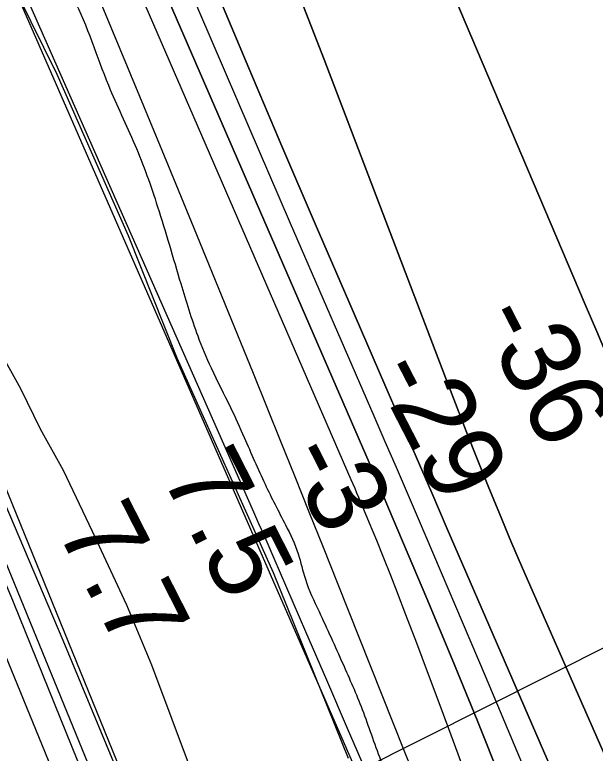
# Model space of a CAD drawing. Extents: x 3684037 to 3722149, y 433263 to 459021.
# Drawn here: x 3708229 to 3708721, y 440941 to 441568 of the extents above; entities that cross this region are included whole.
import ezdxf

# ---------------------------------------------------------------- set-up
doc = ezdxf.new("R2010")
doc.units = 0
for name, color, linetype in [('V-FLOD-BASE', 7, 'Continuous'), ('V-LEVE-TOET', 7, 'Continuous'), ('V-RIVR-EDGE', 7, 'Continuous'), ('V-RIVR-RANG', 7, 'Continuous'), ('V-RRAP-FSHR', 7, 'Continuous'), ('V-SITE-VEGE', 7, 'Continuous'), ('V-SURV-LINE', 7, 'Continuous'), ('V-TOPO-DPTH', 7, 'Continuous'), ('V-TOPO-MINR', 7, 'Continuous'), ('V-TOPO-WATR', 7, 'Continuous'), ('V-UTIL-IDEN', 7, 'Continuous')]:
    doc.layers.add(name, color=color, linetype=linetype)

msp = doc.modelspace()

# ---------------------------------------------------------------- linework, layer by layer
at = {"layer": 'V-FLOD-BASE'}
msp.add_lwpolyline([(3708655.953, 440022.846), (3708571.096, 440224.43700000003), (3708471.115, 440472.954), (3708336.848, 440799.67100000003), (3708227.5670000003, 441069.62), (3708110.161, 441351.732), (3708024.131, 441566.072), (3707971.184, 441738.141), (3707949.653, 441811.721)], dxfattribs=at)
at = {"layer": 'V-LEVE-TOET'}
msp.add_lwpolyline([(3708329.4450000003, 440893.404), (3708269.701, 441036.97500000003), (3708174.0530000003, 441261.768), (3708096.1550000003, 441453.563), (3708080.201, 441490.052), (3708065.4560000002, 441529.456), (3708040.023, 441605.28500000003), (3707987.7630000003, 441786.817), (3707911.21, 442041.826), (3707839.258, 442289.753)], dxfattribs=at)
at = {"layer": 'V-RIVR-EDGE'}
msp.add_spline([(3705459.2609885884, 448025.4338505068), (3705478.181262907, 447991.0156329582), (3705490.6466582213, 447962.67892349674), (3705497.886274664, 447946.89059973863), (3705515.196078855, 447915.30695303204), (3705550.2240541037, 447853.7561290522), (3705577.199678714, 447806.37815928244), (3705592.0892782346, 447777.22671585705), (3705613.0133912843, 447735.5248869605), (3705627.0852571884, 447702.7361373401), (3705648.4127376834, 447660.6289412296), (3705670.9403216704, 447613.2619701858), (3705688.6394949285, 447575.6118136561), (3705703.1157281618, 447542.82206415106), (3705728.0505183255, 447487.76611454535), (3705750.155737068, 447433.12153145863), (3705764.2256032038, 447399.5240471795), (3705787.557922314, 447350.5376070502), (3705800.426685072, 447321.79553037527), (3705823.7710027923, 447277.66149819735), (3705853.129836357, 447212.8897339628), (3705867.200702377, 447179.69661701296), (3705884.5115064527, 447148.517337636), (3705906.216357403, 447095.49122375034), (3705936.00155575, 447039.61454087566), (3705952.47362864, 446996.3062413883), (3705954.4714680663, 446986.5964260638), (3705964.512659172, 446959.0744505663), (3705978.185157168, 446928.3085374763), (3706001.9328423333, 446883.76913808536), (3706017.2158104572, 446850.1686541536), (3706031.3046743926, 446824.25414913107), (3706060.2971362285, 446774.8493432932), (3706084.8695541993, 446736.77782140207), (3706095.754475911, 446723.40670266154), (3706096.150844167, 446720.17076414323), (3706091.2844378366, 446714.52162014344), (3706089.663968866, 446713.31251769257), (3706090.461704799, 446708.86247730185), (3706096.1148483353, 446705.61354028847), (3706102.9840935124, 446703.5747056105), (3706108.6282380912, 446696.68646263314), (3706116.2782211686, 446683.3233429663), (3706129.961717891, 446657.0054704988), (3706163.363224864, 446591.8193400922), (3706169.3887394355, 446575.6296486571), (3706187.0869128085, 446537.5751247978), (3706212.808440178, 446473.6210941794), (3706230.094247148, 446432.33263156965), (3706247.398052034, 446398.3227808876), (3706265.123222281, 446371.18617491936), (3706278.8077188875, 446345.27266978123), (3706293.681320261, 446309.65134908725), (3706314.591434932, 446262.28837758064), (3706333.5067098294, 446225.8483233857), (3706356.038293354, 446180.09882165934), (3706380.1853464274, 446133.5365857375), (3706396.283048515, 446102.36030601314), (3706412.7941168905, 446074.82233236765), (3706429.688555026, 446038.79164492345), (3706446.9753618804, 445997.9075496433), (3706455.379085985, 445962.3022270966), (3706478.2400455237, 445886.2241757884), (3706492.7132791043, 445852.221324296), (3706510.4004537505, 445809.7187598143), (3706528.098627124, 445771.6642359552), (3706558.2621958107, 445705.27300263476), (3706582.809616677, 445657.09229751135), (3706597.6902172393, 445624.3015481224), (3706628.25915314, 445558.3136822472), (3706659.6138263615, 445483.02336802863), (3706677.6863705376, 445432.8368244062), (3706696.968017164, 445381.0298118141), (3706750.0515385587, 445262.4181996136), (3706782.6343120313, 445193.1903956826), (3706806.7693664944, 445141.77575180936), (3706827.6774813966, 445093.60404564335), (3706850.971804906, 445029.251647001), (3706864.204939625, 444984.33387727), (3706871.8019288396, 444949.5392891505), (3706889.464106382, 444896.92754143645), (3706899.900665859, 444865.76526009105), (3706912.3530626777, 444832.1717753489), (3706928.848132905, 444798.1639244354), (3706942.5356291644, 444773.46352128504), (3706966.274315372, 444725.28481592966), (3706990.4233682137, 444679.53131466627), (3707016.9756276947, 444624.4713655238), (3707033.864066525, 444586.0144741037), (3707080.5137064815, 444481.9760839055), (3707095.3833083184, 444444.7372938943), (3707112.268747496, 444405.0673004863), (3707123.1276722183, 444381.1826311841), (3707171.385782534, 444273.5009354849), (3707203.15082239, 444200.6358253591), (3707218.0214241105, 444163.8014026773), (3707250.203829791, 444096.19206794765), (3707257.428447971, 444074.33823424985), (3707269.882844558, 444041.55348416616), (3707288.3577562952, 443990.55720600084), (3707304.028093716, 443950.0814775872), (3707342.974756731, 443837.9747386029), (3707365.860713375, 443772.0058705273), (3707378.693480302, 443728.70656999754), (3707379.8705864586, 443714.14634649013), (3707381.055691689, 443702.8210616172), (3707387.4745748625, 443682.1823296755), (3707398.330499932, 443657.0845583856), (3707418.0505099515, 443619.02503510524), (3707438.977622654, 443578.5363081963), (3707454.253591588, 443542.10525295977), (3707473.1368701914, 443492.7254442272), (3707483.176061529, 443464.3947340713), (3707531.0578012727, 443368.0363234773), (3707542.7274604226, 443344.9583890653), (3707550.7628130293, 443323.91129025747), (3707556.775329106, 443302.4648235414), (3707556.7633304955, 443297.61241559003), (3707558.764169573, 443289.1157022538), (3707568.429989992, 443273.3213791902), (3707583.724956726, 443244.5733032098), (3707593.778146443, 443221.9037356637), (3707598.205189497, 443213.40102302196), (3707609.506477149, 443204.8813123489), (3707611.9086839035, 443195.17049714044), (3707611.872688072, 443180.6132732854), (3707615.480997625, 443168.06888711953), (3707621.9068799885, 443150.26072648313), (3707634.3842739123, 443126.77642497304), (3707648.071770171, 443102.0760218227), (3707655.300387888, 443081.8396574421), (3707660.5361656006, 443073.3349450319), (3707674.23066105, 443051.46511318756), (3707678.635706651, 443034.0663193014), (3707682.6333852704, 443015.4554233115), (3707689.4656347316, 442998.4549974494), (3707701.917031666, 442964.4571453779), (3707713.9590618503, 442928.4384565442), (3707721.175680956, 442903.349684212), (3707726.3964604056, 442888.7794618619), (3707738.081117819, 442871.7670373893), (3707743.706264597, 442857.1958151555), (3707744.4850027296, 442845.0627955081), (3707747.2685794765, 442826.050531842), (3707753.7124597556, 442815.5209831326), (3707762.977912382, 442801.34512927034), (3707770.2135292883, 442783.9393361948), (3707772.585739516, 442762.0975011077), (3707776.166052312, 442738.23082972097), (3707779.760363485, 442720.02530094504), (3707786.591613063, 442702.6205077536), (3707805.499888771, 442663.34988225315), (3707822.7986942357, 442627.3181949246), (3707832.0301507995, 442599.39385186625), (3707839.2457700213, 442573.9007122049), (3707845.6846508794, 442561.3493268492), (3707852.5368980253, 442552.4362475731), (3707860.193880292, 442541.9036992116), (3707869.4663321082, 442530.55841665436), (3707886.3937664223, 442507.8718510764), (3707898.8601616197, 442479.9395089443), (3707916.135969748, 442434.60737304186), (3707928.5753680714, 442395.7571130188), (3707943.439970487, 442356.49648636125), (3707965.5811850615, 442316.40912712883), (3707989.726238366, 442269.0381565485), (3708009.8426166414, 442227.7426947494), (3708024.7172178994, 442192.5257413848), (3708061.3216672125, 442114.39185736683), (3708074.19742916, 442088.4803519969), (3708094.3098078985, 442045.5674208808), (3708116.024657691, 441996.5849802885), (3708126.0638490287, 441968.25427013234), (3708137.690513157, 441927.7885405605), (3708147.3253371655, 441899.4588302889), (3708157.761896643, 441868.2965489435), (3708179.0553810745, 441812.4408636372), (3708203.964174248, 441746.87136346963), (3708227.690861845, 441693.8402501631), (3708249.813078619, 441646.06991167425), (3708265.103045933, 441615.29999904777), (3708271.524928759, 441595.87436909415), (3708278.365177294, 441582.10888186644), (3708308.1063807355, 441508.4400365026), (3708330.6259656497, 441457.8381268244), (3708349.905612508, 441405.22237957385), (3708369.558630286, 441340.0702452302), (3708384.005866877, 441295.5538431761), (3708395.2611598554, 441268.4332353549), (3708411.757229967, 441234.82975177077), (3708423.4208898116, 441209.32561338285), (3708441.1150636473, 441169.65362020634), (3708458.4178686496, 441135.239402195), (3708469.274793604, 441110.54599823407), (3708475.28730968, 441089.09953151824), (3708486.945970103, 441061.5735564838), (3708507.055349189, 441017.44752338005), (3708523.5384208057, 440978.58726451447), (3708539.202758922, 440935.68533212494), (3708564.1435483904, 440883.0555864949), (3708587.089498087, 440841.3487581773), (3708595.1408488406, 440826.77153663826), (3708600.3546291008, 440809.3707429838), (3708606.7475152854, 440778.2184604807), (3708615.5866031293, 440755.14752525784), (3708636.8620896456, 440692.013228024), (3708652.91879648, 440644.25788779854), (3708673.412545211, 440592.04350822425), (3708688.685514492, 440554.3993509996), (3708705.9553233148, 440506.6410111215), (3708725.6613349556, 440462.92034523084), (3708743.353509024, 440422.43961739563), (3708759.4422121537, 440387.62403170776), (3708800.050339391, 440293.3054556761), (3708820.961453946, 440246.3468514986), (3708835.028320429, 440211.5362652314), (3708849.1041858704, 440180.3649849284), (3708876.059812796, 440124.89966857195), (3708892.157514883, 440093.72338884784), (3708912.2798924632, 440054.8541310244), (3708922.3300825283, 440030.97146149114), (3708931.9579073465, 439999.8111799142), (3708939.1845252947, 439978.7660808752), (3708948.0196136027, 439954.0776763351), (3708952.412660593, 439931.82647449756), (3708956.0019723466, 439911.59910907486), (3708960.015649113, 439899.45809035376), (3708969.6484733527, 439870.3196454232), (3708986.9362800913, 439829.8399174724), (3708999.3836774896, 439794.22459608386), (3709014.653647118, 439755.36733687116), (3709034.7480279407, 439705.1757938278), (3709046.79605743, 439671.58330896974), (3709063.280128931, 439633.1274174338), (3709075.7695214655, 439614.49552387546), (3709093.103322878, 439592.6166930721), (3709105.998082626, 439574.38816695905), (3709121.705415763, 439548.8740297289), (3709151.4686166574, 439484.1012656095), (3709171.5959936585, 439447.2538444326), (3709197.377514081, 439407.5618535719), (3709211.0500120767, 439376.7959404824), (3709222.3063049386, 439350.0796999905), (3709240.400846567, 439308.789237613), (3709252.8692415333, 439281.6656301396), (3709266.1473710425, 439254.94439022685), (3709270.9767816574, 439245.6319430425), (3709296.338936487, 439199.87544212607), (3709313.2213760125, 439158.99234673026), (3709331.3089184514, 439114.8713130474), (3709341.338110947, 439082.49692959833), (3709360.25438573, 439046.46124273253), (3709378.7622936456, 439008.80908643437), (3709407.717759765, 438944.44268941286), (3709416.407475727, 438923.6321006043)], degree=3, dxfattribs=at)
at = {"layer": 'V-RIVR-RANG'}
msp.add_line((3708319.1132000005, 440825.27049999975), (3708998.1321000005, 441166.64039999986), dxfattribs=at)
at = {"layer": 'V-RRAP-FSHR'}
for points in [[(3707275.154863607, 443771.4072567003), (3708786.0361450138, 440314.0350934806), (3709222.0934795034, 438921.3709975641)], [(3709200.4250000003, 438921.235), (3709188.2, 438975.89), (3709081.992, 439212.059), (3708987.099, 439411.844), (3708916.306, 439573.43200000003), (3708676.386, 440059.424), (3708454.74, 440592.12200000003), (3708052.683, 441579.782), (3707944.372, 441937.206), (3707632.811, 442977.512), (3707556.2430000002, 443134.009), (3707319.723, 443635.882)]]:
    msp.add_lwpolyline(points, dxfattribs=at)
at = {"layer": 'V-SITE-VEGE'}
for points in [[(3708269.934, 441181.261), (3708250.458, 441216.37), (3708233.971, 441250.735), (3708216.7430000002, 441281.363), (3708192.008, 441338.893), (3708174.759, 441385.219), (3708162.008, 441421.08400000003), (3708153.761, 441441.256), (3708141.0160000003, 441472.63800000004), (3708104.3000000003, 441548.84), (3708090.8000000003, 441586.197), (3708079.546, 441622.814), (3708069.031, 441661.672), (3708007.526, 441838.01300000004), (3707976.744, 441950.852), (3707954.046, 442061.657), (3707919.329, 442186.782)], [(3708008.644, 442157.204), (3708091.0640000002, 441994.341), (3708103.063, 441960.717), (3708127.827, 441879.268), (3708146.603, 441805.286), (3708169.113, 441733.55100000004), (3708199.856, 441653.605), (3708230.5840000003, 441586.365), (3708264.304, 441517.634), (3708325.015, 441380.912), (3708366.251, 441277.056), (3708447.946, 441094.759), (3708511.6720000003, 440937.11)], [(3708413.122, 440833.836), (3708344.883, 441016.147), (3708323.893, 441066.954), (3708294.664, 441129.71), (3708269.934, 441181.261)]]:
    msp.add_lwpolyline(points, dxfattribs=at)
at = {"layer": 'V-SURV-LINE'}
for points in [[(3708038.7450004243, 441548.75442255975), (3708670.0374785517, 440004.8612832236)], [(3708642.27273785, 439993.4982175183), (3708010.9802905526, 441537.39128145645)]]:
    msp.add_lwpolyline(points, dxfattribs=at)
at = {"layer": 'V-TOPO-DPTH'}
for points in [[(3707771.34, 442984.16000000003), (3708145.170398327, 442084.14554148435), (3708156.85360117, 442056.08693645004), (3708168.5694781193, 442028.0420147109), (3708180.3343662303, 442000.0176179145), (3708192.1319284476, 441972.006904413), (3708228.467923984, 441885.9454586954), (3708258.560119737, 441814.95798427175), (3708288.788486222, 441744.0287745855), (3708319.221108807, 441673.1869620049), (3708349.7899021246, 441602.40341416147), (3708523.7871581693, 441201.093698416), (3708529.3498738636, 441188.21904241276), (3708534.8907832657, 441175.33504113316), (3708540.398983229, 441162.4370219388), (3708545.8853769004, 441149.5296574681), (3708578.464186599, 441072.6133977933), (3708599.970032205, 441021.1383346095), (3708621.13782245, 440969.52655543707), (3708641.7985296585, 440917.70970228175)], [(3708641.7985296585, 440917.70970228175), (3708621.13782245, 440969.52655543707), (3708599.970032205, 441021.1383346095), (3708578.464186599, 441072.6133977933), (3708545.8853769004, 441149.5296574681), (3708540.398983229, 441162.4370219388), (3708534.8907832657, 441175.33504113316), (3708529.3498738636, 441188.21904241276), (3708523.7871581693, 441201.093698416), (3708349.7899021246, 441602.40341416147), (3708319.221108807, 441673.1869620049), (3708288.788486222, 441744.0287745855), (3708258.560119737, 441814.95798427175), (3708228.467923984, 441885.9454586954), (3708192.1319284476, 441972.006904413), (3708180.3343662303, 442000.0176179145), (3708168.5694781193, 442028.0420147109), (3708156.85360117, 442056.08693645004), (3708145.170398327, 442084.14554148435), (3707771.34, 442984.16000000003)], [(3708709.870800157, 440868.57363529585), (3708595.781401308, 441131.8114475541), (3708582.5323741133, 441162.37974210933), (3708569.2828071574, 441192.94780270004), (3708556.032430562, 441223.5155123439), (3708542.7815142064, 441254.0829880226), (3708512.159733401, 441324.71935358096), (3708483.7195669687, 441390.6568542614), (3708455.4421222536, 441456.6637096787), (3708427.4087601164, 441522.7745972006), (3708399.5381196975, 441588.954839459), (3708215.8067283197, 442027.4975893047), (3708212.4666078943, 442035.48625685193), (3708209.1342115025, 442043.4781385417), (3708205.8134011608, 442051.474841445), (3708202.5003148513, 442059.47475849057), (3708154.4324801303, 442175.77970447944)], [(3708154.4324801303, 442175.77970447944), (3708202.5003148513, 442059.47475849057), (3708205.8134011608, 442051.474841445), (3708209.1342115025, 442043.4781385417), (3708212.4666078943, 442035.48625685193), (3708215.8067283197, 442027.4975893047), (3708399.5381196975, 441588.954839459), (3708427.4087601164, 441522.7745972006), (3708455.4421222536, 441456.6637096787), (3708483.7195669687, 441390.6568542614), (3708512.159733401, 441324.71935358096), (3708542.7815142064, 441254.0829880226), (3708556.032430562, 441223.5155123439), (3708569.2828071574, 441192.94780270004), (3708582.5323741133, 441162.37974210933), (3708595.781401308, 441131.8114475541), (3708709.870800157, 440868.57363529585)], [(3708068.57925163, 442138.1876600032), (3708086.3673393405, 442095.5563353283), (3708087.5154071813, 442092.804368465), (3708104.7195587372, 442051.5449005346), (3708121.9140457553, 442010.28140738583), (3708139.0940359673, 441969.01187641), (3708156.264361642, 441927.7383202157), (3708334.5443219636, 441498.98151528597), (3708358.826440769, 441440.3446441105), (3708382.995240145, 441381.6612939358), (3708406.9940603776, 441322.9082252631), (3708430.8795611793, 441264.10867759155), (3708454.2502159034, 441206.3368630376), (3708466.335495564, 441176.37638161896), (3708478.380905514, 441146.39992554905), (3708490.3665108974, 441116.39950750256), (3708502.3122465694, 441086.38311480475), (3708558.7794256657, 440944.08357560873), (3708599.490422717, 440843.14048317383)], [(3709009.52, 440303.11), (3708669.687304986, 441075.3251492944), (3708659.658509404, 441098.39599814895), (3708649.769239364, 441121.5257582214), (3708640.08925764, 441144.74388512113), (3708630.5488014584, 441168.020923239), (3708621.182264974, 441191.36938258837), (3708611.9080620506, 441214.7541449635), (3708602.772359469, 441238.19336187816), (3708593.7289904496, 441261.66888181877), (3708491.1548153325, 441530.3054668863), (3708456.1600394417, 441620.4667499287), (3708420.5087869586, 441710.3635082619), (3708383.872819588, 441799.8634795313), (3708346.5803756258, 441889.0989260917), (3708290.1373106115, 442022.10221289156), (3708280.546887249, 442044.62597398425), (3708270.920441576, 442067.13427770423), (3708261.2399624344, 442089.61939536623), (3708251.523460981, 442112.08905565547)], [(3708251.523460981, 442112.08905565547), (3708261.2399624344, 442089.61939536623), (3708270.920441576, 442067.13427770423), (3708280.546887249, 442044.62597398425), (3708290.1373106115, 442022.10221289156), (3708346.5803756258, 441889.0989260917), (3708383.872819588, 441799.8634795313), (3708420.5087869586, 441710.3635082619), (3708456.1600394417, 441620.4667499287), (3708491.1548153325, 441530.3054668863), (3708593.7289904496, 441261.66888181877), (3708602.772359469, 441238.19336187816), (3708611.9080620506, 441214.7541449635), (3708621.182264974, 441191.36938258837), (3708630.5488014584, 441168.020923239), (3708640.08925764, 441144.74388512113), (3708649.769239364, 441121.5257582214), (3708659.658509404, 441098.39599814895), (3708669.687304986, 441075.3251492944), (3709009.52, 440303.11)], [(3708872.2300191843, 440930.33706423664), (3708841.615073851, 441010.216581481), (3708809.771911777, 441089.64147170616), (3708751.4464032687, 441230.41736832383), (3708741.873967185, 441253.43330763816), (3708732.25996335, 441276.4318042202), (3708722.5836078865, 441299.40413670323), (3708712.8656846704, 441322.359026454), (3708601.3264724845, 441584.8356907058), (3708564.404036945, 441672.1000228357), (3708527.6632193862, 441759.44042188), (3708491.1948287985, 441846.89492129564), (3708454.9080561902, 441934.4254876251), (3708394.6830918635, 442080.341947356), (3708388.7726595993, 442095.01977278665), (3708383.0322990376, 442109.76213709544)], [(3708383.0322990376, 442109.76213709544), (3708388.7726595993, 442095.01977278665), (3708394.6830918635, 442080.341947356), (3708454.9080561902, 441934.4254876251), (3708491.1948287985, 441846.89492129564), (3708527.6632193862, 441759.44042188), (3708564.404036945, 441672.1000228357), (3708601.3264724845, 441584.8356907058), (3708712.8656846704, 441322.359026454), (3708722.5836078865, 441299.40413670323), (3708732.25996335, 441276.4318042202), (3708741.873967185, 441253.43330763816), (3708751.4464032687, 441230.41736832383), (3708809.771911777, 441089.64147170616), (3708841.615073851, 441010.216581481), (3708872.2300191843, 440930.33706423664)]]:
    msp.add_lwpolyline(points, dxfattribs=at)
at = {"layer": 'V-TOPO-MINR'}
for points in [[(3707771.34, 442984.16000000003), (3708145.170398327, 442084.14554148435), (3708156.85360117, 442056.08693645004), (3708168.5694781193, 442028.0420147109), (3708180.3343662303, 442000.0176179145), (3708192.1319284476, 441972.006904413), (3708228.467923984, 441885.9454586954), (3708258.560119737, 441814.95798427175), (3708288.788486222, 441744.0287745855), (3708319.221108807, 441673.1869620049), (3708349.7899021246, 441602.40341416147), (3708523.7871581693, 441201.093698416), (3708529.3498738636, 441188.21904241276), (3708534.8907832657, 441175.33504113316), (3708540.398983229, 441162.4370219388), (3708545.8853769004, 441149.5296574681), (3708578.464186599, 441072.6133977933), (3708599.970032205, 441021.1383346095), (3708621.13782245, 440969.52655543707), (3708641.7985296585, 440917.70970228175)], [(3707801.7887286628, 442673.47377900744), (3708038.3471030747, 442055.8862848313), (3708051.433371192, 442022.16523735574), (3708064.716031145, 441988.5227262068), (3708078.2932788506, 441954.99801954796), (3708092.066918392, 441921.551849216), (3708105.0423174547, 441890.4323717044), (3708125.6043500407, 441841.5512221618), (3708146.370861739, 441792.7578603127), (3708167.444092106, 441744.09618000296), (3708188.7218015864, 441695.5222873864), (3708431.366484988, 441146.30974953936), (3708435.6756196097, 441136.5194213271), (3708439.966557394, 441126.7211543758), (3708444.2301999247, 441116.9109793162), (3708448.475645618, 441107.0928655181), (3708475.3837260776, 441044.6260789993), (3708493.1071248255, 441003.58493350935), (3708510.880604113, 440962.56554215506), (3708528.72920421, 440921.5787820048)], [(3708011.2639211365, 442464.3307038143), (3708173.8811918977, 442071.80641804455), (3708181.3652279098, 442053.78233578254), (3708188.868489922, 442035.76627876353), (3708196.400590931, 442017.76225960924), (3708203.9519179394, 441999.76626569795), (3708285.135170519, 441806.72719654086), (3708329.0736442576, 441702.7292044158), (3708373.2401646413, 441598.82859519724), (3708417.7487549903, 441495.0740603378), (3708462.485391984, 441391.4169083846), (3708533.386949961, 441227.87526921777), (3708542.8237515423, 441206.0533367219), (3708552.2337590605, 441184.2198854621), (3708561.6035754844, 441162.3691560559), (3708570.946597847, 441140.5069078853), (3708627.843029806, 441007.0321421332), (3708665.2477252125, 440918.2735668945)], [(3708154.4324801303, 442175.77970447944), (3708202.5003148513, 442059.47475849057), (3708205.8134011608, 442051.474841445), (3708209.1342115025, 442043.4781385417), (3708212.4666078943, 442035.48625685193), (3708215.8067283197, 442027.4975893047), (3708399.5381196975, 441588.954839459), (3708427.4087601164, 441522.7745972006), (3708455.4421222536, 441456.6637096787), (3708483.7195669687, 441390.6568542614), (3708512.159733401, 441324.71935358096), (3708542.7815142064, 441254.0829880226), (3708556.032430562, 441223.5155123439), (3708569.2828071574, 441192.94780270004), (3708582.5323741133, 441162.37974210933), (3708595.781401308, 441131.8114475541), (3708709.870800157, 440868.57363529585)], [(3708251.523460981, 442112.08905565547), (3708261.2399624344, 442089.61939536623), (3708270.920441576, 442067.13427770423), (3708280.546887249, 442044.62597398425), (3708290.1373106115, 442022.10221289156), (3708346.5803756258, 441889.0989260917), (3708383.872819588, 441799.8634795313), (3708420.5087869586, 441710.3635082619), (3708456.1600394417, 441620.4667499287), (3708491.1548153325, 441530.3054668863), (3708593.7289904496, 441261.66888181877), (3708602.772359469, 441238.19336187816), (3708611.9080620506, 441214.7541449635), (3708621.182264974, 441191.36938258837), (3708630.5488014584, 441168.020923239), (3708640.08925764, 441144.74388512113), (3708649.769239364, 441121.5257582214), (3708659.658509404, 441098.39599814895), (3708669.687304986, 441075.3251492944), (3709009.52, 440303.11)], [(3708383.0322990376, 442109.76213709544), (3708388.7726595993, 442095.01977278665), (3708394.6830918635, 442080.341947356), (3708454.9080561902, 441934.4254876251), (3708491.1948287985, 441846.89492129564), (3708527.6632193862, 441759.44042188), (3708564.404036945, 441672.1000228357), (3708601.3264724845, 441584.8356907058), (3708712.8656846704, 441322.359026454), (3708722.5836078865, 441299.40413670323), (3708732.25996335, 441276.4318042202), (3708741.873967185, 441253.43330763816), (3708751.4464032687, 441230.41736832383), (3708809.771911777, 441089.64147170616), (3708841.615073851, 441010.216581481), (3708872.2300191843, 440930.33706423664)], [(3708229.8642478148, 441828.91857520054), (3708513.9701382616, 441173.70348005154), (3708515.577096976, 441169.98233597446), (3708517.176682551, 441166.2580380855), (3708518.7652084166, 441162.5290094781), (3708520.3463611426, 441158.7968270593), (3708529.5927717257, 441136.8809450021), (3708535.713045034, 441122.1569386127), (3708541.7286059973, 441107.3909198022), (3708547.587098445, 441092.56188235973), (3708553.340878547, 441077.69083249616), (3708560.379665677, 441059.20768990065), (3708569.5363806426, 441035.0493427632), (3708578.642558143, 441010.8720514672), (3708587.672929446, 440986.6663439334), (3708596.6527632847, 440962.4416922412), (3708685.6509197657, 440721.1946799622)]]:
    msp.add_lwpolyline(points, dxfattribs=at)
at = {"layer": 'V-TOPO-WATR'}
msp.add_lwpolyline([(3708068.57925163, 442138.1876600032), (3708086.3673393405, 442095.5563353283), (3708087.5154071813, 442092.804368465), (3708104.7195587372, 442051.5449005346), (3708121.9140457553, 442010.28140738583), (3708139.0940359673, 441969.01187641), (3708156.264361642, 441927.7383202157), (3708334.5443219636, 441498.98151528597), (3708358.826440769, 441440.3446441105), (3708382.995240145, 441381.6612939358), (3708406.9940603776, 441322.9082252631), (3708430.8795611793, 441264.10867759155), (3708454.2502159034, 441206.3368630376), (3708466.335495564, 441176.37638161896), (3708478.380905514, 441146.39992554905), (3708490.3665108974, 441116.39950750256), (3708502.3122465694, 441086.38311480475), (3708558.7794256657, 440944.08357560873), (3708599.490422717, 440843.14048317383)], dxfattribs=at)
at = {"layer": 'V-UTIL-IDEN'}
msp.add_lwpolyline([(3709200.4250000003, 438921.235), (3709188.2, 438975.89), (3709081.992, 439212.059), (3708987.099, 439411.844), (3708916.306, 439573.43200000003), (3708676.386, 440059.424), (3708454.74, 440592.12200000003), (3708052.683, 441579.782), (3707944.372, 441937.206), (3707632.811, 442977.512), (3707556.2430000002, 443134.009), (3707319.723, 443635.882)], dxfattribs=at)

# ---------------------------------------------------------------- texts
at = {"layer": 'V-RIVR-RANG'}
for s, height, rotation, p in [('-36', 66.99999999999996, 297.2626111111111, (3708620.629366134, 441311.324305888)), ('-29', 66.99999999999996, 297.2626111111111, (3708531.9868542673, 441265.0338720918)), ('7.5', 67, 296.97832571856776, (3708352.3462380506, 441177.95276961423)), ('-3', 67, 296.97832571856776, (3708456.30829834, 441194.15544906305)), ('7.7', 67, 296.97832571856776, (3708263.3412380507, 441132.36576961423))]:
    msp.add_text(s, height=height, rotation=rotation, dxfattribs=at).set_placement(p)

doc.saveas('drawing.dxf')
